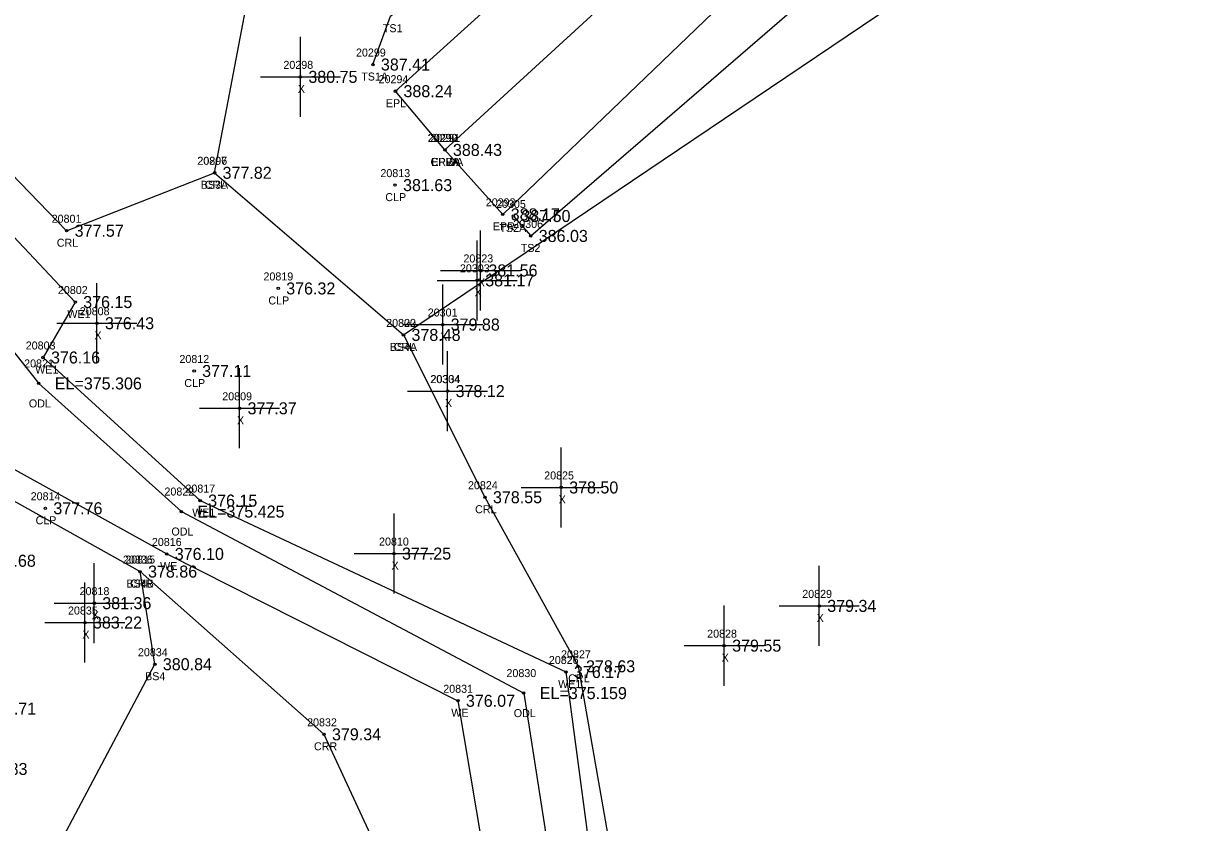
# Model space of a CAD drawing. Extents: x 2116373 to 2118139, y 979529 to 981026.
# Drawn here: x 2117341.9 to 2117487.1, y 980101.3 to 980201.2 of the extents above; entities that cross this region are included whole.
import ezdxf

# ---------------------------------------------------------------- set-up
doc = ezdxf.new("R2010")
doc.units = 0
for name, color, linetype in [('RD_DTM_BkLn1', 7, 'Continuous'), ('RD_DTM_BkLn2', 7, 'Continuous'), ('RD_DTM_BkLn_txCode', 7, 'Continuous'), ('RD_EX_H2O', 7, 'Continuous'), ('RD_EX_H2O_txCode', 7, 'Continuous'), ('RD_EX_Misc', 7, 'Continuous'), ('RD_EX_Misc_txCode', 7, 'Continuous'), ('RD_EX_Road', 7, 'Continuous'), ('RD_EX_Road_txCode', 7, 'Continuous'), ('RD_EX_TX_H2O_ELEV', 7, 'Continuous'), ('RD_EX_TX_Misc_ELEV', 7, 'Continuous'), ('RD_EX_TX_Road_ELEV', 7, 'Continuous'), ('RD_HC_Survey_ELEV', 7, 'Continuous'), ('RD_HC_Survey_txCode', 7, 'Continuous'), ('RD_SMD_Locator', 7, 'Continuous')]:
    doc.layers.add(name, color=color, linetype=linetype)

msp = doc.modelspace()

# ---------------------------------------------------------------- linework, layer by layer
at = {"layer": 'RD_DTM_BkLn1'}
msp.add_lwpolyline([(2117394.63, 980185.41), (2117475.35, 980259.39), (2117549.63, 980326.58), (2117623.5, 980394.2), (2117697.55, 980461.75), (2117735.02, 980495.39), (2117805.43, 980566.78), (2117837.53, 980605.36), (2117867.93, 980645.06), (2117897.09, 980686.34), (2117923.66, 980727.51), (2117948.72, 980771.39), (2117971.22, 980818.34), (2117988.96, 980866.05), (2117991.42, 980873.14), (2118004.26, 980915.09), (2118016.82, 980963.49), (2118028.02, 981013.26)], dxfattribs=at)
at = {"layer": 'RD_DTM_BkLn2'}
for points in [[(2117403.18, 980177.15), (2117405.35, 980174.66), (2117487.26, 980245.43), (2117563.99, 980312.17), (2117634.65, 980381.46), (2117704.3, 980451.46), (2117722.65, 980465.11), (2117743.87, 980484.9), (2117780.03, 980521.07), (2117815.83, 980557.8), (2117846.79, 980597.78), (2117878.62, 980636.27), (2117911.26, 980677.34), (2117934.7, 980720.41), (2117959.82, 980759.29), (2117971.51, 980778.31), (2117986.8, 980774.26), (2117987.85, 980770.9), (2117995.22, 980745.17), (2118001.26, 980694.98), (2118008.4, 980640.04)], [(2117389.45, 980162.29), (2117496.47, 980234.47), (2117570.67, 980306.14), (2117640.42, 980376.1), (2117709.81, 980445.93), (2117716.62, 980450.81)], [(2117385.63, 980196.08), (2117387.84, 980202.12), (2117465.94, 980270.83), (2117486.04, 980295), (2117483.25, 980299), (2117479.87, 980302.1)], [(2117365.85, 980182.55), (2117371.24, 980211.01), (2117380.62, 980221.24)], [(2117344.8, 980095.54), (2117358.39, 980121.14), (2117356.54, 980132.72)]]:
    msp.add_lwpolyline(points, dxfattribs=at)
at = {"layer": 'RD_EX_H2O'}
for points in [[(2117055.27, 980533.4), (2117084.87, 980468.5), (2117113.12, 980396.82), (2117150.26, 980360.48), (2117172.14, 980330.53), (2117167.4, 980300.56), (2117152, 980282.05), (2117153.33, 980268.31), (2117164.01, 980260.72), (2117221.6, 980247.26), (2117265.25, 980211.02), (2117324.27, 980199.15), (2117347.37, 980175.31), (2117365.85, 980182.55), (2117389.45, 980162.29), (2117399.63, 980142.01), (2117411.26, 980120.88), (2117420.42, 980068.64), (2117446.24, 980057.21), (2117497.11, 980045.39), (2117594.71, 979999.33), (2117646.33, 979985.56), (2117750.91, 980032.44), (2117805.09, 980018.87)], [(2117320.83, 980195.76), (2117348.44, 980166.4), (2117344.42, 980159.47), (2117364.05, 980141.59), (2117409.75, 980120.17), (2117416.75, 980067.62), (2117432.5, 980045.49), (2117502.17, 980039.14), (2117583.98, 979987.26), (2117646.81, 979981.12), (2117705, 980001.51), (2117745.64, 980024.24), (2117805.06, 980014.37)], [(2117253.76, 980181.57), (2117309.73, 980180.01), (2117328.75, 980169.13), (2117302.89, 980172.19), (2117303.47, 980157.54), (2117331.87, 980146.51), (2117356.54, 980132.72), (2117379.52, 980112.38), (2117402.94, 980061.78), (2117424.79, 980029.41), (2117490.12, 980015.27), (2117551.05, 979984.61)], [(2117327.56, 980176.76), (2117343.89, 980156.23), (2117361.71, 980140.22), (2117404.48, 980117.53), (2117412.59, 980065.44), (2117429.85, 980042.55), (2117500.31, 980032.76), (2117583.13, 979982.49), (2117644.33, 979974.23), (2117711.62, 979990.62), (2117746.36, 980006.72), (2117805.28, 980007.14)], [(2117334.27, 980149.08), (2117359.88, 980134.92), (2117396.25, 980116.57), (2117405.43, 980061.84), (2117428.2, 980035.31), (2117491.98, 980017.16), (2117553.53, 979985.3), (2117578.12, 979975.29), (2117646.29, 979963.95), (2117711.26, 979981.91), (2117748.87, 979990.36), (2117810.8, 979988.9)]]:
    msp.add_lwpolyline(points, dxfattribs=at)
at = {"layer": 'RD_EX_Misc'}
for p, q in [((2117376.57, 980189.54), (2117376.57, 980199.54)), ((2117371.57, 980194.54), (2117381.57, 980194.54)), ((2117399.06, 980165.35), (2117399.06, 980175.35)), ((2117398.66, 980164.11), (2117398.66, 980174.11)), ((2117394.06, 980170.35), (2117404.06, 980170.35)), ((2117351.16, 980158.75), (2117351.16, 980168.75)), ((2117393.66, 980169.11), (2117403.66, 980169.11)), ((2117394.35, 980158.59), (2117394.35, 980168.59)), ((2117346.16, 980163.75), (2117356.16, 980163.75)), ((2117389.35, 980163.59), (2117399.35, 980163.59)), ((2117394.96, 980150.27), (2117394.96, 980160.27)), ((2117394.96, 980150.27), (2117394.96, 980160.27)), ((2117368.97, 980148.12), (2117368.97, 980158.12)), ((2117389.96, 980155.27), (2117399.96, 980155.27)), ((2117389.96, 980155.27), (2117399.96, 980155.27)), ((2117363.97, 980153.12), (2117373.97, 980153.12)), ((2117409.15, 980138.23), (2117409.15, 980148.23)), ((2117404.15, 980143.23), (2117414.15, 980143.23)), ((2117388.27, 980129.97), (2117388.27, 980139.97)), ((2117350.82, 980123.77), (2117350.82, 980133.77)), ((2117383.27, 980134.97), (2117393.27, 980134.97)), ((2117441.39, 980123.43), (2117441.39, 980133.43)), ((2117349.66, 980121.35), (2117349.66, 980131.35)), ((2117345.82, 980128.77), (2117355.82, 980128.77)), ((2117429.51, 980118.46), (2117429.51, 980128.46)), ((2117436.39, 980128.43), (2117446.39, 980128.43)), ((2117344.66, 980126.35), (2117354.66, 980126.35)), ((2117424.51, 980123.46), (2117434.51, 980123.46))]:
    msp.add_line(p, q, dxfattribs=at)
at = {"layer": 'RD_EX_Road'}
for points in [[(2117394.63, 980185.41), (2117388.45, 980192.75), (2117469.76, 980266.25), (2117487.02, 980282.1), (2117515.02, 980307.24), (2117543.53, 980333.04), (2117617.72, 980400.8), (2117691.88, 980468.07), (2117729.57, 980501.96), (2117798.93, 980572.83), (2117831.02, 980611), (2117861.69, 980650.07), (2117890.37, 980690.61), (2117916.67, 980731.93), (2117941.38, 980774.84), (2117963.75, 980821.95), (2117981.56, 980869.78), (2117996.2, 980917.73), (2118008.9, 980966.42), (2118019.55, 981015.46)], [(2117394.63, 980185.41), (2117401.85, 980177.36), (2117480.62, 980253.04), (2117556.27, 980319.95), (2117629.74, 980387.35), (2117703.2, 980454.29), (2117741.39, 980488.9), (2117777.53, 980523.58), (2117812.39, 980561.12), (2117844.66, 980599.64), (2117874.87, 980639.35), (2117904.78, 980681.4), (2117931.2, 980722.71), (2117957.05, 980767.35), (2117963.67, 980781.11), (2117980.28, 980814.62), (2117994.42, 980851.98)]]:
    msp.add_lwpolyline(points, dxfattribs=at)
at = {"layer": 'RD_SMD_Locator'}
for centre in [(2117385.63, 980196.08), (2117376.57, 980194.54), (2117388.45, 980192.75), (2117394.63, 980185.41), (2117394.63, 980185.41), (2117394.63, 980185.41), (2117365.85, 980182.55), (2117365.85, 980182.55), (2117388.4, 980181.01), (2117401.85, 980177.36), (2117403.18, 980177.15), (2117347.37, 980175.31), (2117405.35, 980174.66), (2117399.06, 980170.35), (2117398.66, 980169.11), (2117373.8, 980168.1), (2117348.44, 980166.4), (2117351.16, 980163.75), (2117394.35, 980163.59), (2117389.45, 980162.29), (2117389.45, 980162.29), (2117344.42, 980159.47), (2117363.3, 980157.78), (2117343.89, 980156.23), (2117394.96, 980155.27), (2117394.96, 980155.27), (2117368.97, 980153.12), (2117409.15, 980143.23), (2117364.05, 980141.59), (2117399.63, 980142.01), (2117344.71, 980140.63), (2117361.71, 980140.22), (2117359.88, 980134.92), (2117388.27, 980134.97), (2117356.54, 980132.72), (2117356.54, 980132.72), (2117350.82, 980128.77), (2117441.39, 980128.43), (2117349.66, 980126.35), (2117429.51, 980123.46), (2117358.39, 980121.14), (2117411.26, 980120.88), (2117409.75, 980120.17), (2117404.48, 980117.53), (2117396.25, 980116.57), (2117379.52, 980112.38)]:
    msp.add_circle(centre, 0.15, dxfattribs=at)

# ---------------------------------------------------------------- texts
at = {"layer": 'RD_DTM_BkLn_txCode'}
for s, p in [('TS1', (2117386.88, 980200.12)), ('20299', (2117383.52, 980197.08)), ('TS1A', (2117384.18, 980194.08)), ('20296', (2117363.71, 980183.55)), ('BS3A', (2117364.13, 980180.55)), ('20305', (2117401.02, 980178.15)), ('TS2A', (2117401.44, 980175.15)), ('20306', (2117403.17, 980175.66)), ('TS2', (2117404.1, 980172.66)), ('20302', (2117387.29, 980163.29)), ('BS4A', (2117387.73, 980160.29)), ('20836', (2117354.4, 980133.72)), ('BS4B', (2117354.84, 980130.72)), ('20834', (2117356.28, 980122.14)), ('BS4', (2117357.17, 980119.14))]:
    msp.add_text(s, height=1, dxfattribs=at).set_placement(p)
at = {"layer": 'RD_EX_H2O_txCode'}
for s, p in [('20807', (2117363.69, 980183.55)), ('CRL', (2117364.62, 980180.55)), ('20801', (2117345.5, 980176.31)), ('CRL', (2117346.14, 980173.31)), ('20802', (2117346.28, 980167.4)), ('WE1', (2117347.46, 980164.4)), ('20820', (2117387.29, 980163.29)), ('20803', (2117342.26, 980160.47)), ('CRL', (2117388.22, 980160.29)), ('20821', (2117342.06, 980158.23)), ('WE1', (2117343.44, 980157.47)), ('ODL', (2117342.65, 980153.23)), ('20824', (2117397.51, 980143.01)), ('20822', (2117359.59, 980142.22)), ('20817', (2117362.21, 980142.59)), ('CRL', (2117398.4, 980140.01)), ('WE1', (2117363.06, 980139.59)), ('ODL', (2117360.46, 980137.22)), ('20816', (2117358.02, 980135.92)), ('20815', (2117354.7, 980133.72)), ('WE', (2117359.04, 980132.92)), ('CRR', (2117355.29, 980130.72)), ('20826', (2117407.61, 980121.17)), ('20827', (2117409.14, 980121.88)), ('20830', (2117402.32, 980119.53)), ('WE1', (2117408.77, 980118.17)), ('CRL', (2117410.03, 980118.88)), ('20831', (2117394.42, 980117.57)), ('WE', (2117395.42, 980114.57)), ('ODL', (2117403.23, 980114.53)), ('20832', (2117377.41, 980113.38)), ('CRR', (2117378.27, 980110.38))]:
    msp.add_text(s, height=1, dxfattribs=at).set_placement(p)
at = {"layer": 'RD_EX_Misc_txCode'}
for s, p in [('20298', (2117374.45, 980195.54)), ('X', (2117376.25, 980192.54)), ('20823', (2117396.94, 980171.35)), ('20303', (2117396.5, 980170.11)), ('X', (2117398.74, 980168.35)), ('X', (2117398.34, 980167.11)), ('20808', (2117349.01, 980164.75)), ('20301', (2117392.48, 980164.59)), ('X', (2117350.85, 980161.75)), ('X', (2117394.04, 980161.59)), ('20304', (2117392.8, 980156.27)), ('20334', (2117392.84, 980156.27)), ('20809', (2117366.81, 980154.12)), ('X', (2117394.64, 980153.27)), ('X', (2117394.64, 980153.27)), ('X', (2117368.65, 980151.12)), ('20825', (2117407.03, 980144.23)), ('X', (2117408.84, 980141.23)), ('20810', (2117386.4, 980135.97)), ('X', (2117387.96, 980132.97)), ('20818', (2117348.99, 980129.77)), ('20829', (2117439.27, 980129.43)), ('20835', (2117347.54, 980127.35)), ('X', (2117350.51, 980126.77)), ('X', (2117441.07, 980126.43)), ('X', (2117349.34, 980124.35)), ('20828', (2117427.39, 980124.46)), ('X', (2117429.2, 980121.46))]:
    msp.add_text(s, height=1, dxfattribs=at).set_placement(p)
at = {"layer": 'RD_EX_Road_txCode'}
for s, p in [('20294', (2117386.34, 980193.75)), ('EPL', (2117387.25, 980190.75)), ('20292', (2117392.51, 980186.41)), ('20291', (2117392.8, 980186.41)), ('EPRA', (2117392.92, 980183.41)), ('EPLA', (2117392.94, 980183.41)), ('20293', (2117399.73, 980178.36)), ('EPR', (2117400.62, 980175.36))]:
    msp.add_text(s, height=1, dxfattribs=at).set_placement(p)
at = {"layer": 'RD_EX_TX_H2O_ELEV'}
for s, p in [('377.82', (2117366.85, 980181.8)), ('377.57', (2117348.37, 980174.56)), ('376.15', (2117349.44, 980165.65)), ('378.48', (2117390.45, 980161.54)), ('376.16', (2117345.42, 980158.72)), ('EL=375.306', (2117345.89, 980155.48)), ('376.15', (2117365.05, 980140.84)), ('378.55', (2117400.63, 980141.26)), ('EL=375.425', (2117363.71, 980139.47)), ('376.10', (2117360.88, 980134.17)), ('378.86', (2117357.54, 980131.97)), ('376.17', (2117410.75, 980119.42)), ('378.63', (2117412.26, 980120.13)), ('EL=375.159', (2117406.48, 980116.78)), ('376.07', (2117397.25, 980115.82)), ('379.34', (2117380.52, 980111.63))]:
    msp.add_text(s, height=1.5, dxfattribs=at).set_placement(p)
at = {"layer": 'RD_EX_TX_Misc_ELEV'}
for s, p in [('387.41', (2117386.63, 980195.33)), ('380.75', (2117377.57, 980193.79)), ('377.82', (2117366.85, 980181.8)), ('387.50', (2117404.18, 980176.4)), ('386.03', (2117406.35, 980173.91)), ('381.17', (2117399.66, 980168.36)), ('381.56', (2117400.06, 980169.6)), ('376.43', (2117352.16, 980163)), ('379.88', (2117395.35, 980162.84)), ('378.48', (2117390.45, 980161.54)), ('378.12', (2117395.96, 980154.52)), ('378.12', (2117395.96, 980154.52)), ('377.37', (2117369.97, 980152.37)), ('378.50', (2117410.15, 980142.48)), ('377.25', (2117389.27, 980134.22)), ('378.86', (2117357.54, 980131.97)), ('381.36', (2117351.82, 980128.02)), ('379.34', (2117442.39, 980127.68)), ('383.22', (2117350.66, 980125.6)), ('379.55', (2117430.51, 980122.71)), ('380.84', (2117359.39, 980120.39)), ('392.71', (2117337.43, 980114.85)), ('391.83', (2117336.34, 980107.3))]:
    msp.add_text(s, height=1.5, dxfattribs=at).set_placement(p)
at = {"layer": 'RD_EX_TX_Road_ELEV'}
for s, p in [('388.24', (2117389.45, 980192)), ('388.43', (2117395.63, 980184.66)), ('388.43', (2117395.63, 980184.66)), ('388.17', (2117402.85, 980176.61))]:
    msp.add_text(s, height=1.5, dxfattribs=at).set_placement(p)
at = {"layer": 'RD_HC_Survey_ELEV'}
for s, p in [('388.43', (2117395.63, 980184.66)), ('381.63', (2117389.4, 980180.26)), ('376.32', (2117374.8, 980167.35)), ('377.11', (2117364.3, 980157.03)), ('377.76', (2117345.71, 980139.88)), ('384.68', (2117337.38, 980133.32))]:
    msp.add_text(s, height=1.5, dxfattribs=at).set_placement(p)
at = {"layer": 'RD_HC_Survey_txCode'}
for s, p in [('20290', (2117392.47, 980186.41)), ('CRWA', (2117392.83, 980183.41)), ('20813', (2117386.57, 980182.01)), ('CLP', (2117387.18, 980179.01)), ('20819', (2117371.96, 980169.1)), ('CLP', (2117372.57, 980166.1)), ('20812', (2117361.46, 980158.78)), ('CLP', (2117362.07, 980155.78)), ('20814', (2117342.88, 980141.63)), ('CLP', (2117343.49, 980138.63))]:
    msp.add_text(s, height=1, dxfattribs=at).set_placement(p)

doc.saveas('drawing.dxf')
